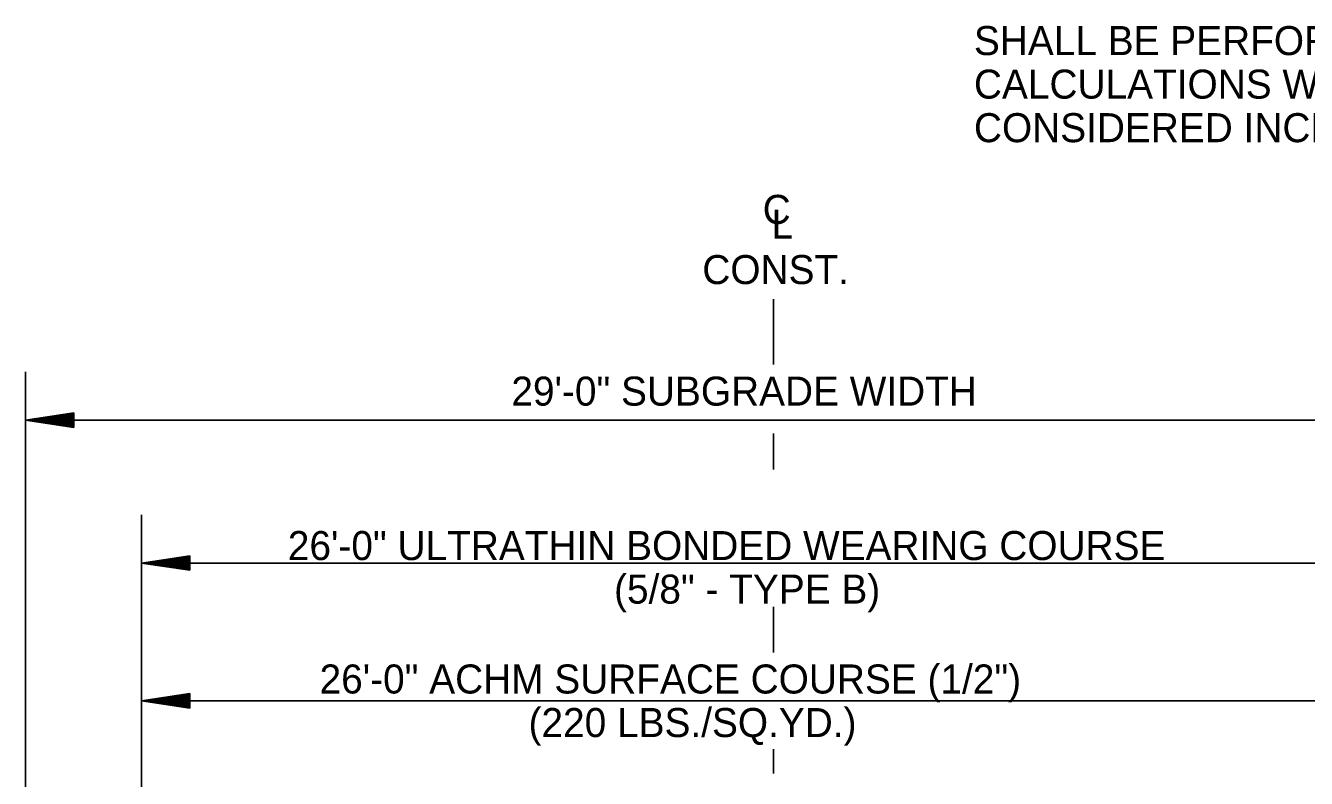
# Model space of a CAD drawing. Extents: x 2263886 to 2266026, y -3122850 to -3121850.
# Drawn here: x 2265465.3 to 2265491.77, y -3122407.03 to -3122391.48 of the extents above; entities that cross this region are included whole.
import ezdxf

# ---------------------------------------------------------------- set-up
doc = ezdxf.new("R2010")
doc.units = 0
doc.layers.add('R_Border Prem', color=7, linetype='Continuous')

msp = doc.modelspace()

# ---------------------------------------------------------------- linework, layer by layer
at = {"layer": 'R_Border Prem'}
for p, q in [((2265480.76, -3122398.48), (2265480.76, -3122397.13)), ((2265465.302, -3122415.554), (2265465.302, -3122398.63)), ((2265466.302, -3122399.48), (2265465.302, -3122399.63)), ((2265466.302, -3122399.505), (2265465.469, -3122399.63)), ((2265466.302, -3122399.48), (2265466.302, -3122399.78)), ((2265465.302, -3122399.63), (2265496.173, -3122399.63)), ((2265466.302, -3122399.78), (2265465.302, -3122399.63)), ((2265466.302, -3122399.755), (2265465.469, -3122399.63)), ((2265466.302, -3122399.531), (2265465.641, -3122399.63)), ((2265466.302, -3122399.73), (2265465.641, -3122399.63)), ((2265466.302, -3122399.556), (2265465.808, -3122399.63)), ((2265466.302, -3122399.705), (2265465.808, -3122399.63)), ((2265466.302, -3122399.582), (2265465.977, -3122399.63)), ((2265466.302, -3122399.679), (2265465.977, -3122399.63)), ((2265466.302, -3122399.607), (2265466.144, -3122399.63)), ((2265466.302, -3122399.654), (2265466.144, -3122399.63)), ((2265480.76, -3122400.653), (2265480.76, -3122399.906)), ((2265467.697, -3122420.933), (2265467.697, -3122401.584)), ((2265468.697, -3122402.434), (2265467.697, -3122402.584)), ((2265468.697, -3122402.434), (2265468.697, -3122402.734)), ((2265467.697, -3122402.584), (2265493.778, -3122402.584)), ((2265468.697, -3122402.734), (2265467.697, -3122402.584)), ((2265468.697, -3122402.459), (2265467.864, -3122402.584)), ((2265468.697, -3122402.709), (2265467.864, -3122402.584)), ((2265468.697, -3122402.485), (2265468.036, -3122402.584)), ((2265468.697, -3122402.684), (2265468.036, -3122402.584)), ((2265468.697, -3122402.51), (2265468.203, -3122402.584)), ((2265468.697, -3122402.659), (2265468.203, -3122402.584)), ((2265468.697, -3122402.536), (2265468.372, -3122402.584)), ((2265468.697, -3122402.633), (2265468.372, -3122402.584)), ((2265468.697, -3122402.561), (2265468.539, -3122402.584)), ((2265468.697, -3122402.608), (2265468.539, -3122402.584)), ((2265480.76, -3122404.433), (2265480.76, -3122403.489)), ((2265468.697, -3122405.283), (2265467.697, -3122405.433)), ((2265468.697, -3122405.308), (2265467.864, -3122405.433)), ((2265468.697, -3122405.334), (2265468.036, -3122405.433)), ((2265468.697, -3122405.283), (2265468.697, -3122405.583)), ((2265467.697, -3122405.433), (2265493.778, -3122405.433)), ((2265468.697, -3122405.583), (2265467.697, -3122405.433)), ((2265468.697, -3122405.558), (2265467.864, -3122405.433)), ((2265468.697, -3122405.533), (2265468.036, -3122405.433)), ((2265468.697, -3122405.359), (2265468.203, -3122405.433)), ((2265468.697, -3122405.508), (2265468.203, -3122405.433)), ((2265468.697, -3122405.385), (2265468.372, -3122405.433)), ((2265468.697, -3122405.482), (2265468.372, -3122405.433)), ((2265468.697, -3122405.41), (2265468.539, -3122405.433)), ((2265468.697, -3122405.457), (2265468.539, -3122405.433)), ((2265480.76, -3122406.933), (2265480.76, -3122406.433))]:
    msp.add_line(p, q, dxfattribs=at)

# ---------------------------------------------------------------- texts
for s, p in [('SHALL BE PERFORMED BEFORE CONSTRUCTING NOTCH AND WIDENING.', (2265484.901, -3122392.085)), ('CALCULATIONS WILL NOT BE PAID FOR DIRECTLY, BUT PAYMENT WILL BE ', (2265484.901, -3122392.985)), ('CONSIDERED INCLUDED IN THE VARIOUS PAY ITEMS.', (2265484.901, -3122393.885)), ('C', (2265480.535, -3122395.574)), ('L', (2265480.716, -3122395.879)), ('CONST.', (2265479.287, -3122396.818)), ('29\'-0" SUBGRADE WIDTH', (2265475.341, -3122399.33))]:
    msp.add_text(s, height=0.6, dxfattribs=at).set_placement(p)
for s, p in [('26\'-0" ULTRATHIN BONDED WEARING COURSE', (2265470.721, -3122402.522)), ('(5/8" - TYPE B)', (2265477.463, -3122403.422)), ('26\'-0" ACHM SURFACE COURSE (1/2")', (2265471.377, -3122405.28)), ('(220 LBS./SQ.YD.)', (2265475.696, -3122406.18))]:
    msp.add_text(s, height=0.6, rotation=360, dxfattribs=at).set_placement(p)

doc.saveas('drawing.dxf')
